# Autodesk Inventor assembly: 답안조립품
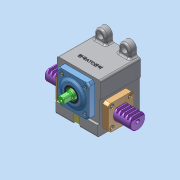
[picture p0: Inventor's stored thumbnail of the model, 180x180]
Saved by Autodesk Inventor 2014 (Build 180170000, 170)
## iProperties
Created: 2024-11
Part Number: 답안조립품
Document SubType Name: Assembly
Designer: dg
Author: dg
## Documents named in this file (10)
- C:\Users\dg\Desktop\741104V1010\답안조립품.iam
- C:\Users\dg\Desktop\741104V1010\본체.ipt
- C:\Users\dg\Desktop\741104V1010\가져온 구성요소\깊음 홈 볼 베어링 6202\깊음 홈 볼 베어링 6202.ipt
- C:\Users\dg\Desktop\741104V1010\가져온 구성요소\피니언 축\피니언 축.ipt
- C:\Users\dg\Desktop\741104V1010\가져온 구성요소\커버\커버.ipt
- C:\Users\dg\Desktop\741104V1010\가져온 구성요소\오일 실 15 25 4\오일 실 15 25 4.ipt
- C:\Users\dg\Desktop\741104V1010\가져온 구성요소\스톱퍼\스톱퍼.ipt
- C:\Users\dg\Desktop\741104V1010\가져온 구성요소\래크\래크.ipt
- C:\Users\dg\Desktop\741104V1010\가져온 구성요소\수지 부시\수지 부시.ipt
- C:\Users\dg\Desktop\741104V1010\가져온 구성요소\육각 소켓 머리 볼트 M4x10\육각 소켓 머리 볼트 M4x10.ipt
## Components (1 placed, 1 different names)
1. 피니언 축:1 — 각도:1
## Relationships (1: Angle 1)
- 각도:1 [Angle]: 피니언 축:1
